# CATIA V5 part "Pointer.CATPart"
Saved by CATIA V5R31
Part number: Part2
Bounding box of the stored display mesh (mm): x -12.875 to 12.875, y -12.732 to 12.732, z 0 to 100
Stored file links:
  D:\PROJECTS\Project 2021\US EDITION\CATIA V5 6R 2021\Resources\Part Files\c16_catia_v5_6r2021_prt\Point Surface Joint-(Fig16-46)\Pointer.CATPart
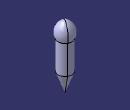
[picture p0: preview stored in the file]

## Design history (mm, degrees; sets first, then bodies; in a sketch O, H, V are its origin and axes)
Body1 (main body)
  Sketch1 on yz-plane, origin (0, 0, 0), H (0, 1, 0), V (0, 0, 1)
    line L1 (0, 0) -> (10.9446, 30.0702)
    point P1 (10.9446, 30.0702)
    line L2 (10.9446, 30.0702) -> (10.9446, 75.0702)
    point P2 (10.9446, 30.0702)
    point P3 (10.9446, 75.0702)
    arc A1 centre (-4.3336, 83.2301) radius 17.3208 from (10.9446, 75.0702) to (0, 100) ccw
    point P5 (0, 100)
    point P6 (10.9446, 91.3901)
    line L3 (0, 0) -> (0, 100)
    reference intersected line E1 through (0, 0) direction (-1, 0) from xy-plane
    reference intersected line E3 through (0, 0) direction (0, 1) from zx-plane
    radius A1 = 17.3208
    angle L1 L3 = 20
    distance O P1 = 32
    distance O P5 = 100
    distance P2 P3 = 45
    coincidence: P2 L1, P5 V, A1 P6, P6 L2, P2 P1, E3 P5, P1 L2
    vertical: L2 V, L3 V, E3 V
    horizontal: E1 H
    perpendicularity: E1 L2
  Shaft1: profile Sketch1, axis Sketch1.L3, angle 360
